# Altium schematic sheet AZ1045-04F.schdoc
size 127 x 101 mm
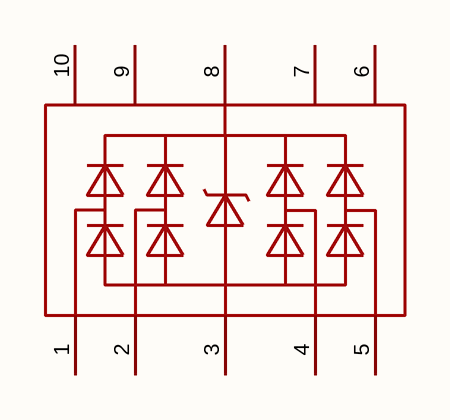
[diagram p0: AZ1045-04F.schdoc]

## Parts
D?  az1045-04f  [DFN2510-10_L2.5-W1.0-P0.50-BL]  (value not drawn)

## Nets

Not connected (* = marked no-connect by the designer): D? 1(I/O_1) 2(I/O_2) 3(GND) 4(I/O_3) 5(I/O_4) 6(NC) 7(NC) 8(GND) 9(NC) 10(NC)

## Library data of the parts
D? = az1045-04f: 极性:单向;反向截止电压(Vrwm):5V;钳位电压:9V；16V;峰值脉冲电流(Ipp):4A@8/20us;峰值脉冲功率(Ppp):80W@8/20us;击穿电压:8V;; Manufacturer: TECH PUBLIC(台舟); AddInBom: yes; ModelId: 55525fa8fc914f7c8ffcb10749ea5f73; ModelName: DFN-10_L2.5-W1.0-H0.5-P0.50; ModelTransform: 40.1574,98.425,0,90,0,0,0,0,0; Polarity: 单向; Reverse Stand-Off Voltage (Vrwm): 5V; Clamping Voltage: 9V；16V; Voltage - Breakdown: 8V; Reverse Leakage Current (Ir): 100nA; Number of Channels: 四路; level of protection: IEC 61000-4-2；IEC 61000-4-4；IEC 61000-4-5; Type: ESD; Junction Capacitance: 0.8pF；0.3pF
